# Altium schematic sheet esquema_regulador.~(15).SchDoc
size A4
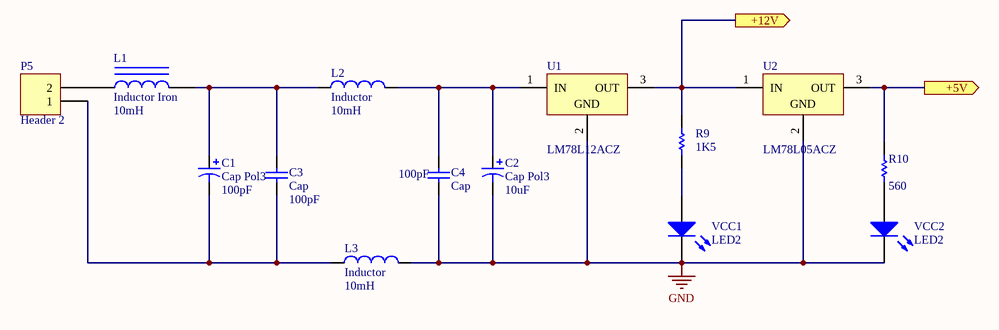
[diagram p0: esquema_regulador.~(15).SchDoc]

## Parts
C1  Cap Pol3  value 100pF  [CAPPR5-10X16]
C2  Cap Pol3  value 10uF  [CAPPR5-10X16]
C3  Cap  value 100pF  [CAPPR2.5-6.3X5]
C4  Cap  value 100pF  [CAPPR2.5-6.3X5]
L1  Inductor Iron  value 10mH  [bobina_Choque]
L2  Inductor  value 10mH  [RAD-0.2]
L3  Inductor  value 10mH  [RAD-0.2]
P5  Header 2  [pwheader1x2]
R9  value 1K5  [AXIAL-0.3]  (hidden comment: Carbon 1/8w 5%)
R10  value 560  [AXIAL-0.3]  (hidden comment: Carbon 1/8w 5%)
U1  LM78L12ACZ  [T03B]
U2  LM78L05ACZ  [T03B]
VCC1  LED2  [CAPPR2.5-6.3X5]
VCC2  LED2  [CAPPR2.5-6.3X5]

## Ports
+5V (out), +12V (out)

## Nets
GND: C2.2 C4.1 L3.2 U1.2(GND) U2.2(GND) VCC1.2(K) VCC2.2(K)
+5V: R10.2 U2.3(OUT) ; port +5V
+12V: R9.2 U1.3(OUT) U2.1(IN) ; port +12V
NetC1_1: C1.1 C3.2 L1.2 L2.1
NetC1_2: C1.2 C3.1 L3.1 P5.1
NetC2_1: C2.1 C4.2 L2.2 U1.1(IN)
NetL1_1: L1.1 P5.2
NetR9_1: R9.1 VCC1.1(A)
NetR10_1: R10.1 VCC2.1(A)

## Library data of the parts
C1 = Cap Pol3: Polarized Capacitor (Surface Mount)
C2 = Cap Pol3: Polarized Capacitor 35V
C3 C4 = Cap: Capacitor
L1 = Inductor Iron: Magnetic-Core Inductor
L2 L3 = Inductor: Code_IEC: 1005
P5 = Header 2: Header, 2-Pin
R9 R10 = Res Semi: Semiconductor Resistor
U1 = LM78L12ACZ: 3-Terminal Positive Regulator; PackageDocument: 2000
U2 = LM78L05ACZ: 3-Terminal Positive Regulator; PackageDocument: 2000
VCC1 VCC2 = LED2: Typical RED, GREEN, YELLOW, AMBER GaAs LED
